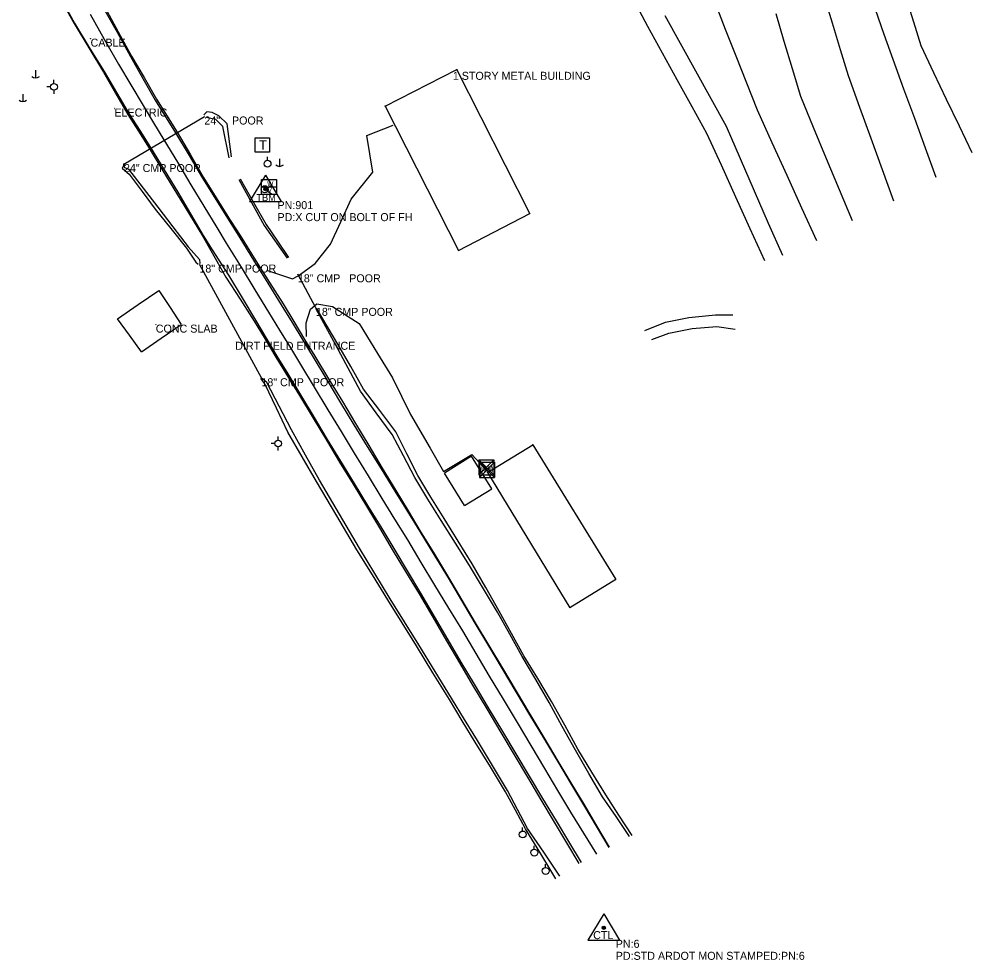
# Model space of a CAD drawing. Extents: x 1734049 to 1769984, y 344166 to 379510.
# Drawn here: x 1736178 to 1736774, y 377458 to 378046 of the extents above; entities that cross this region are included whole.
import ezdxf

# ---------------------------------------------------------------- set-up
doc = ezdxf.new("R2010")
doc.units = 0
for name, color, linetype in [('S_BUILDING', 7, 'Continuous'), ('S_CROSS_DRAIN', 7, 'Continuous'), ('S_CROSS_DRAIN_ANNOT', 7, 'Continuous'), ('S_DITCHLINE', 7, 'Continuous'), ('S_DRG_PT_SYM', 7, 'Continuous'), ('S_DRIVEWAY', 7, 'Continuous'), ('S_EDGE_CONCRETE', 7, 'Continuous'), ('S_EDGE_PAVEMENT', 7, 'Continuous'), ('S_ELECTRIC_UTILITIES_ANNOT', 7, 'Continuous'), ('S_MSC_PT_SYM', 7, 'Continuous'), ('S_PAVEMENT_CROWN', 7, 'Continuous'), ('S_PRIMARY_CTL', 7, 'Continuous'), ('S_PRIMARY_CTL_ANNOT', 7, 'Continuous'), ('S_SHOULDER', 7, 'Continuous'), ('S_SIDE_DRAIN', 7, 'Continuous'), ('S_SIDE_DRAIN_ANNOT', 7, 'Continuous'), ('S_STR_PT_SYM', 7, 'Continuous'), ('S_STREAM', 7, 'Continuous'), ('S_SURVEY_TEXT_ANNOT', 7, 'Continuous'), ('S_TELEPHONE_UTILITIES', 7, 'Continuous'), ('S_TRAILS', 7, 'Continuous'), ('S_UTILITY_POLE', 7, 'Continuous'), ('S_UTL_PT_SYM', 7, 'Continuous'), ('S_WATER_UTILITIES', 7, 'Continuous')]:
    doc.layers.add(name, color=color, linetype=linetype)

msp = doc.modelspace()

# ---------------------------------------------------------------- linework, layer by layer
at = {"layer": 'S_BUILDING'}
for p, q in [((1736407.06, 377991.82), (1736451.95, 378014.7)), ((1736497.58, 377924.73), (1736451.95, 378014.7)), ((1736407.06, 377991.82), (1736452.99, 377901.55)), ((1736452.99, 377901.55), (1736497.58, 377924.73)), ((1736471.16, 377762.94), (1736499.35, 377780.23)), ((1736499.35, 377780.23), (1736551.19, 377696.06)), ((1736471.16, 377762.94), (1736522.51, 377678.34)), ((1736551.19, 377696.06), (1736522.51, 377678.34))]:
    msp.add_line(p, q, dxfattribs=at)
at = {"layer": 'S_CROSS_DRAIN'}
msp.add_line((1736243.87, 377955.57), (1736294.14, 377985.27), dxfattribs=at)
at = {"layer": 'S_DITCHLINE'}
for points in [[(1736311.18, 377960.13), (1736308.43, 377980.73), (1736303.24, 377985.59), (1736299.03, 377987.68), (1736295.57, 377988.23), (1736293.81, 377986.28)], [(1736309.61, 377959.44), (1736305.68, 377979.09), (1736301.29, 377983.37), (1736297.18, 377984.2), (1736295.15, 377984.75)], [(1736243.79, 377955.98), (1736243.28, 377954.19), (1736242.84, 377952.93), (1736244.36, 377951.44), (1736247.07, 377949.28), (1736255.27, 377938.36), (1736263.47, 377927.43), (1736273.23, 377915.21), (1736283, 377902.99), (1736288.74, 377894.32), (1736290.32, 377893.02)], [(1736244.24, 377955), (1736243.85, 377953.55), (1736246.66, 377952.34), (1736255.8, 377940.52), (1736264.94, 377928.71), (1736274.46, 377916.25), (1736283.98, 377903.79), (1736291.09, 377895.86), (1736291.37, 377893.39)], [(1736315.57, 377945.98), (1736323.57, 377931.63), (1736331.57, 377917.27), (1736345.79, 377896.77)], [(1736316.45, 377946.31), (1736324.58, 377932.05), (1736332.7, 377917.78), (1736339.73, 377907.44), (1736346.76, 377897.09)], [(1736559.85, 377535.39), (1736551.4, 377547.84), (1736542.95, 377560.29), (1736534.46, 377574.82), (1736525.98, 377589.35), (1736517.83, 377604.23), (1736509.69, 377619.11), (1736501.21, 377633.49), (1736492.74, 377647.87), (1736484.98, 377661.79), (1736477.23, 377675.7), (1736468.52, 377690.28), (1736459.8, 377704.85), (1736450.97, 377718.81), (1736442.13, 377732.78), (1736433.84, 377746.29), (1736425.56, 377759.81), (1736418.54, 377773.18), (1736411.52, 377786.54), (1736401.58, 377800.15), (1736391.64, 377813.75), (1736384, 377828.07), (1736376.36, 377842.39), (1736370.08, 377853.81), (1736363.8, 377865.23)], [(1736561.46, 377536.06), (1736553.24, 377548.77), (1736545.01, 377561.48), (1736536.28, 377575.73), (1736527.55, 377589.98), (1736519.34, 377604.94), (1736511.14, 377619.89), (1736502.43, 377634.14), (1736493.72, 377648.39), (1736486.06, 377662.27), (1736478.39, 377676.15), (1736469.95, 377690.94), (1736461.51, 377705.73), (1736452.7, 377719.89), (1736443.89, 377734.05), (1736435.68, 377747.47), (1736427.47, 377760.89), (1736420.65, 377774.58), (1736413.83, 377788.28), (1736403.71, 377801.58), (1736393.59, 377814.88), (1736385.56, 377828.99), (1736377.53, 377843.1), (1736370.9, 377854.35), (1736364.27, 377865.61)], [(1736513.77, 377509.09), (1736504.35, 377524.65), (1736494.92, 377540.21), (1736488.62, 377551.81), (1736482.31, 377563.41), (1736472.85, 377578.92), (1736463.39, 377594.43), (1736455.31, 377607.74), (1736447.23, 377621.05), (1736437.01, 377637.79), (1736426.78, 377654.52), (1736417.81, 377668.86), (1736408.84, 377683.21), (1736399.17, 377698.84), (1736389.51, 377714.48), (1736376.81, 377735.81), (1736364.1, 377757.15), (1736355.19, 377772.6), (1736346.28, 377788.06), (1736339.12, 377803.13), (1736331.95, 377818.2), (1736330.04, 377820.85), (1736329.48, 377821.63)], [(1736516.34, 377510.77), (1736506.23, 377525.66), (1736496.12, 377540.55), (1736489.87, 377552.35), (1736483.62, 377564.14), (1736474.23, 377579.77), (1736464.84, 377595.39), (1736456.7, 377608.64), (1736448.56, 377621.89), (1736438.35, 377638.56), (1736428.13, 377655.24), (1736419.17, 377669.61), (1736410.21, 377683.98), (1736400.64, 377699.78), (1736391.06, 377715.59), (1736378.57, 377736.79), (1736366.09, 377757.99), (1736357.36, 377773.72), (1736348.63, 377789.44), (1736340.9, 377804.26), (1736333.18, 377819.07), (1736330.38, 377821.44), (1736330.03, 377821.84)]]:
    msp.add_lwpolyline(points, dxfattribs=at)
at = {"layer": 'S_DRG_PT_SYM'}
for points in [[(1736294.14, 377985.27), (1736294.14, 377985.32), (1736294.14, 377985.27), (1736294.09, 377985.27), (1736294.14, 377985.27), (1736294.14, 377985.22), (1736294.14, 377985.27), (1736294.19, 377985.27)], [(1736243.87, 377955.57), (1736243.87, 377955.62), (1736243.87, 377955.57), (1736243.82, 377955.57), (1736243.87, 377955.57), (1736243.87, 377955.52), (1736243.87, 377955.57), (1736243.92, 377955.57)], [(1736291.01, 377892.78), (1736291.01, 377892.83), (1736291.01, 377892.78), (1736290.96, 377892.78), (1736291.01, 377892.78), (1736291.01, 377892.73), (1736291.01, 377892.78), (1736291.06, 377892.78)], [(1736352.57, 377886.68), (1736352.57, 377886.73), (1736352.57, 377886.68), (1736352.52, 377886.68), (1736352.57, 377886.68), (1736352.57, 377886.63), (1736352.57, 377886.68), (1736352.62, 377886.68)], [(1736363.84, 377865.72), (1736363.84, 377865.77), (1736363.84, 377865.72), (1736363.79, 377865.72), (1736363.84, 377865.72), (1736363.84, 377865.67), (1736363.84, 377865.72), (1736363.89, 377865.72)], [(1736329.77, 377821.75), (1736329.77, 377821.8), (1736329.77, 377821.75), (1736329.72, 377821.75), (1736329.77, 377821.75), (1736329.77, 377821.7), (1736329.77, 377821.75), (1736329.82, 377821.75)]]:
    msp.add_lwpolyline(points, dxfattribs=at)
at = {"layer": 'S_DRIVEWAY'}
for points in [[(1736332.86, 377889.34), (1736349.22, 377883.93), (1736352.82, 377885.81), (1736363.37, 377893.49), (1736372.94, 377905.43), (1736379.42, 377919.56), (1736385.9, 377933.69), (1736399.34, 377950.44), (1736395.72, 377973.3), (1736412.14, 377979.85)], [(1736357.92, 377847.85), (1736357.81, 377856.36), (1736360.41, 377865), (1736364.36, 377868.33), (1736374.28, 377866.51), (1736390.96, 377855.95), (1736402.39, 377837.13), (1736411.65, 377822.05), (1736417.25, 377810.55), (1736422.85, 377799.06), (1736435.17, 377778.14), (1736443.53, 377763.58), (1736461.32, 377774.13), (1736471.11, 377763.53)]]:
    msp.add_lwpolyline(points, dxfattribs=at)
at = {"layer": 'S_EDGE_CONCRETE'}
for points in [[(1736254.73, 377838.24), (1736247.3, 377848.59), (1736239.86, 377858.93), (1736252.81, 377867.77), (1736265.76, 377876.61), (1736272.7, 377865.93), (1736279.65, 377855.25)], [(1736254.73, 377838.24), (1736267.19, 377846.74), (1736279.65, 377855.25)], [(1736456.77, 377742.17), (1736473.7, 377752.55), (1736461.04, 377773.03), (1736444.19, 377762.54)], [(1736456.77, 377742.17), (1736444.19, 377762.54)]]:
    msp.add_lwpolyline(points, dxfattribs=at)
at = {"layer": 'S_EDGE_PAVEMENT'}
for points in [[(1736202.97, 378061.85), (1736212.99, 378043.66), (1736222.2, 378028.48), (1736231.41, 378013.31), (1736239.21, 378000.18), (1736247, 377987.06), (1736253.71, 377976.45), (1736260.42, 377965.85), (1736268.94, 377951.87), (1736277.46, 377937.9), (1736285.46, 377924.42), (1736293.47, 377910.93), (1736299.04, 377902.04), (1736309.15, 377886.04), (1736317.64, 377872.04), (1736326.14, 377858.04), (1736332.83, 377846.75), (1736339.51, 377835.46), (1736345.59, 377825.52), (1736354.13, 377811.32), (1736362.67, 377797.12), (1736370.97, 377783.49), (1736379.27, 377769.86), (1736387.69, 377756.08), (1736396.11, 377742.3), (1736404.35, 377728.88), (1736412.58, 377715.47), (1736420.85, 377701.52), (1736429.11, 377687.57), (1736437.68, 377672.91), (1736446.26, 377658.25), (1736454.5, 377644.42), (1736462.74, 377630.6), (1736471.59, 377615.84), (1736480.43, 377601.09), (1736488.75, 377587.1), (1736497.07, 377573.11), (1736505.52, 377559.17), (1736513.97, 377545.24), (1736521.79, 377532.24), (1736529.61, 377519.24)], [(1736231.18, 378053.03), (1736239.54, 378037.86), (1736247.91, 378022.69), (1736255.69, 378009.1), (1736263.46, 377995.51), (1736276.16, 377975.1), (1736284.59, 377960.91), (1736293.02, 377946.71), (1736301.34, 377933.42), (1736309.66, 377920.14), (1736315.65, 377910.5), (1736325.41, 377894.49), (1736333.8, 377881.06), (1736342.19, 377867.63), (1736348.92, 377856.54), (1736355.64, 377845.45), (1736362.02, 377834.87), (1736370.63, 377820.65), (1736379.23, 377806.42), (1736387.6, 377792.72), (1736395.96, 377779.01), (1736404.57, 377765.11), (1736413.19, 377751.21), (1736421, 377738.58), (1736428.81, 377725.95), (1736437.6, 377711.53), (1736446.39, 377697.11), (1736454.73, 377682.9), (1736463.07, 377668.69), (1736471.69, 377654.47), (1736480.3, 377640.25), (1736488.86, 377625.9), (1736497.42, 377611.54), (1736506.09, 377596.99), (1736514.76, 377582.43), (1736522.87, 377568.86), (1736530.97, 377555.28), (1736538.97, 377541.97), (1736546.96, 377528.66)]]:
    msp.add_lwpolyline(points, dxfattribs=at)
at = {"layer": 'S_MSC_PT_SYM'}
for points in [[(1736449.41, 378013.18), (1736449.41, 378013.23), (1736449.41, 378013.18), (1736449.36, 378013.18), (1736449.41, 378013.18), (1736449.41, 378013.13), (1736449.41, 378013.18), (1736449.46, 378013.18)], [(1736263.75, 377855.25), (1736263.75, 377855.3), (1736263.75, 377855.25), (1736263.7, 377855.25), (1736263.75, 377855.25), (1736263.75, 377855.2), (1736263.75, 377855.25), (1736263.8, 377855.25)], [(1736313.42, 377844.52), (1736313.42, 377844.57), (1736313.42, 377844.52), (1736313.37, 377844.52), (1736313.42, 377844.52), (1736313.42, 377844.47), (1736313.42, 377844.52), (1736313.47, 377844.52)]]:
    msp.add_lwpolyline(points, dxfattribs=at)
at = {"layer": 'S_PAVEMENT_CROWN'}
msp.add_lwpolyline([(1736222.68, 378049.1), (1736231.55, 378033.57), (1736240.41, 378018.04), (1736248.09, 378005.04), (1736255.78, 377992.05), (1736262.25, 377981.34), (1736268.72, 377970.63), (1736277.24, 377956.66), (1736285.76, 377942.68), (1736293.85, 377929.28), (1736301.93, 377915.87), (1736307.8, 377906.2), (1736317.05, 377891.05), (1736325.62, 377877.01), (1736334.19, 377862.98), (1736341.05, 377851.81), (1736347.92, 377840.64), (1736354.22, 377830.31), (1736362.77, 377816.12), (1736371.31, 377801.93), (1736379.55, 377788.43), (1736387.78, 377774.93), (1736396.46, 377760.8), (1736405.13, 377746.67), (1736413.05, 377733.72), (1736420.97, 377720.77), (1736429.51, 377706.64), (1736438.04, 377692.5), (1736446.73, 377678.18), (1736455.42, 377663.86), (1736463.76, 377649.77), (1736472.1, 377635.67), (1736480.85, 377621.2), (1736489.6, 377606.72), (1736498.17, 377592.29), (1736506.75, 377577.86), (1736514.89, 377564.23), (1736523.02, 377550.59), (1736531.06, 377537.48), (1736539.1, 377524.37)], dxfattribs=at)
at = {"layer": 'S_PRIMARY_CTL'}
for p, q in [((1736332.32, 377948.6), (1736322.29, 377932.09)), ((1736332.32, 377948.6), (1736342.15, 377932.09)), ((1736322.29, 377932.09), (1736342.15, 377932.09)), ((1736543.71, 377487.1), (1736533.68, 377470.59)), ((1736543.71, 377487.1), (1736553.54, 377470.59)), ((1736533.68, 377470.59), (1736553.54, 377470.59))]:
    msp.add_line(p, q, dxfattribs=at)
for centre, radius in [((1736332.32, 377939.9), 1.04), ((1736332.32, 377939.9), 0.609), ((1736332.32, 377939.9), 0.344), ((1736543.71, 377478.4), 1.04), ((1736543.71, 377478.4), 0.609), ((1736543.71, 377478.4), 0.344)]:
    msp.add_circle(centre, radius, dxfattribs=at)
at = {"layer": 'S_SHOULDER'}
for points in [[(1736202.57, 378061.64), (1736212.65, 378043.47), (1736221.83, 378028.26), (1736231, 378013.04), (1736238.67, 377999.83), (1736246.34, 377986.62), (1736252.99, 377976.01), (1736259.64, 377965.4), (1736268.18, 377951.42), (1736276.73, 377937.43), (1736284.88, 377924.05), (1736293.02, 377910.67), (1736298.13, 377901.46), (1736307.54, 377884.97), (1736316.42, 377871.21), (1736325.31, 377857.46), (1736332.04, 377846.19), (1736338.77, 377834.93), (1736344.82, 377825.08), (1736353.49, 377810.94), (1736362.15, 377796.79), (1736370.39, 377783.1), (1736378.63, 377769.41), (1736387.07, 377755.6), (1736395.51, 377741.79), (1736403.5, 377728.3), (1736411.49, 377714.82), (1736419.9, 377700.92), (1736428.32, 377687.02), (1736436.9, 377672.39), (1736445.48, 377657.77), (1736453.64, 377643.87), (1736461.8, 377629.98), (1736470.64, 377615.23), (1736479.49, 377600.49), (1736487.81, 377586.49), (1736496.14, 377572.5), (1736504.42, 377558.46), (1736512.7, 377544.42), (1736520.47, 377531.47), (1736528.24, 377518.52)], [(1736231.88, 378053.49), (1736240.27, 378038.26), (1736248.66, 378023.03), (1736256.45, 378009.6), (1736264.24, 377996.18), (1736277.08, 377975.56), (1736285.35, 377961.33), (1736293.62, 377947.1), (1736301.89, 377933.77), (1736310.17, 377920.43), (1736316.39, 377911.02), (1736326.19, 377895.02), (1736334.81, 377881.62), (1736343.42, 377868.23), (1736350.11, 377857.12), (1736356.8, 377846.01), (1736363.08, 377835.52), (1736371.78, 377821.33), (1736380.47, 377807.14), (1736388.65, 377793.46), (1736396.83, 377779.79), (1736405.28, 377765.65), (1736413.73, 377751.52), (1736421.41, 377738.91), (1736429.08, 377726.29), (1736437.91, 377711.81), (1736446.74, 377697.32), (1736455.06, 377683.11), (1736463.37, 377668.91), (1736471.88, 377654.76), (1736480.39, 377640.6), (1736488.99, 377626.22), (1736497.6, 377611.84), (1736506.33, 377597.22), (1736515.07, 377582.6), (1736523.17, 377569.08), (1736531.28, 377555.55), (1736539.2, 377542.18), (1736547.12, 377528.82)]]:
    msp.add_lwpolyline(points, dxfattribs=at)
at = {"layer": 'S_SIDE_DRAIN'}
for p, q in [((1736291.01, 377892.78), (1736329.77, 377821.75)), ((1736363.84, 377865.72), (1736352.57, 377886.68))]:
    msp.add_line(p, q, dxfattribs=at)
at = {"layer": 'S_STR_PT_SYM'}
for points in [[(1736451.95, 378014.7), (1736451.95, 378014.75), (1736451.95, 378014.7), (1736451.9, 378014.7), (1736451.95, 378014.7), (1736451.95, 378014.65), (1736451.95, 378014.7), (1736452, 378014.7)], [(1736451.95, 378014.7), (1736451.95, 378014.75), (1736451.95, 378014.7), (1736451.9, 378014.7), (1736451.95, 378014.7), (1736451.95, 378014.65), (1736451.95, 378014.7), (1736452, 378014.7)], [(1736407.06, 377991.82), (1736407.06, 377991.87), (1736407.06, 377991.82), (1736407.01, 377991.82), (1736407.06, 377991.82), (1736407.06, 377991.77), (1736407.06, 377991.82), (1736407.11, 377991.82)], [(1736407.06, 377991.82), (1736407.06, 377991.87), (1736407.06, 377991.82), (1736407.01, 377991.82), (1736407.06, 377991.82), (1736407.06, 377991.77), (1736407.06, 377991.82), (1736407.11, 377991.82)], [(1736497.58, 377924.73), (1736497.58, 377924.78), (1736497.58, 377924.73), (1736497.53, 377924.73), (1736497.58, 377924.73), (1736497.58, 377924.68), (1736497.58, 377924.73), (1736497.63, 377924.73)], [(1736452.99, 377901.55), (1736452.99, 377901.6), (1736452.99, 377901.55), (1736452.94, 377901.55), (1736452.99, 377901.55), (1736452.99, 377901.5), (1736452.99, 377901.55), (1736453.04, 377901.55)], [(1736499.35, 377780.23), (1736499.35, 377780.28), (1736499.35, 377780.23), (1736499.3, 377780.23), (1736499.35, 377780.23), (1736499.35, 377780.18), (1736499.35, 377780.23), (1736499.4, 377780.23)], [(1736471.16, 377762.94), (1736471.16, 377762.99), (1736471.16, 377762.94), (1736471.11, 377762.94), (1736471.16, 377762.94), (1736471.16, 377762.89), (1736471.16, 377762.94), (1736471.21, 377762.94)], [(1736471.16, 377762.94), (1736471.16, 377762.99), (1736471.16, 377762.94), (1736471.11, 377762.94), (1736471.16, 377762.94), (1736471.16, 377762.89), (1736471.16, 377762.94), (1736471.21, 377762.94)], [(1736551.19, 377696.06), (1736551.19, 377696.11), (1736551.19, 377696.06), (1736551.14, 377696.06), (1736551.19, 377696.06), (1736551.19, 377696.01), (1736551.19, 377696.06), (1736551.24, 377696.06)], [(1736522.51, 377678.34), (1736522.51, 377678.39), (1736522.51, 377678.34), (1736522.46, 377678.34), (1736522.51, 377678.34), (1736522.51, 377678.29), (1736522.51, 377678.34), (1736522.56, 377678.34)], [(1736522.51, 377678.34), (1736522.51, 377678.39), (1736522.51, 377678.34), (1736522.46, 377678.34), (1736522.51, 377678.34), (1736522.51, 377678.29), (1736522.51, 377678.34), (1736522.56, 377678.34)]]:
    msp.add_lwpolyline(points, dxfattribs=at)
at = {"layer": 'S_STREAM'}
for points in [[(1736562.24, 378058.44), (1736570.99, 378041.76), (1736580.23, 378025.04), (1736589.47, 378008.32), (1736598.72, 377991.59), (1736607.96, 377974.87), (1736617.01, 377954.98), (1736626.05, 377935.09), (1736635.1, 377915.2), (1736644.14, 377895.31)], [(1736613.05, 378056.67), (1736619.68, 378039.88), (1736626.31, 378023.1), (1736632.95, 378006.31), (1736639.58, 377989.52), (1736648.85, 377969.08), (1736658.12, 377948.64), (1736667.39, 377928.2), (1736676.65, 377907.76)], [(1736681.58, 378060.15), (1736686.54, 378043.69), (1736691.5, 378027.23), (1736696.46, 378010.78), (1736703.53, 377991.2), (1736710.6, 377971.63), (1736717.67, 377952.06), (1736724.74, 377932.48)], [(1736732.77, 378059.2), (1736737.29, 378044.38), (1736741.81, 378029.55), (1736749.82, 378012.84), (1736757.83, 377996.14), (1736765.83, 377979.43), (1736773.84, 377962.72)], [(1736651.18, 378049.6), (1736656.33, 378032.41), (1736661.47, 378015.22), (1736666.62, 377998.02), (1736674.7, 377978.57), (1736682.78, 377959.11), (1736690.86, 377939.66), (1736698.94, 377920.2)], [(1736713.3, 378052.38), (1736718.85, 378036.73), (1736724.41, 378021.08), (1736731.14, 378002.64), (1736737.87, 377984.2), (1736744.61, 377965.76), (1736751.34, 377947.32)], [(1736581.88, 378048.31), (1736591.46, 378031.02), (1736601.04, 378013.73), (1736610.63, 377996.44), (1736620.21, 377979.16), (1736629, 377959), (1736637.79, 377938.85), (1736646.58, 377918.7), (1736655.37, 377898.54)]]:
    msp.add_lwpolyline(points, dxfattribs=at)
at = {"layer": 'S_TELEPHONE_UTILITIES'}
msp.add_lwpolyline([(1736325.79, 377962.95), (1736325.79, 377971.95), (1736334.79, 377971.95), (1736334.79, 377962.95)], close=True, dxfattribs=at)
at = {"layer": 'S_TRAILS'}
for points in [[(1736569.33, 377851.49), (1736582.32, 377856.71), (1736596.89, 377859.78), (1736613.52, 377861.45), (1736624.42, 377861.3)], [(1736573.87, 377845.97), (1736584.5, 377849.85), (1736598.97, 377852.91), (1736614.41, 377854.16), (1736625.77, 377852.38)]]:
    msp.add_lwpolyline(points, dxfattribs=at)
at = {"layer": 'S_UTILITY_POLE'}
for p, q in [((1736188.58, 378014.14), (1736188.58, 378009.41)), ((1736200.12, 378005.91), (1736200.12, 378008.16)), ((1736198.03, 378003.78), (1736195.7, 378003.78)), ((1736200.2, 377999.36), (1736200.2, 378001.69)), ((1736180.59, 377999.28), (1736180.59, 377994.55)), ((1736333.49, 377957.93), (1736333.49, 377960.04)), ((1736341.09, 377958.83), (1736341.09, 377954.1)), ((1736338.14, 377780.94), (1736335.81, 377780.94)), ((1736340.23, 377783.07), (1736340.23, 377785.32)), ((1736340.31, 377776.52), (1736340.31, 377778.85)), ((1736492.94, 377538.89), (1736492.94, 377541)), ((1736500.17, 377527.5), (1736500.17, 377529.61)), ((1736507.29, 377516.09), (1736507.29, 377518.19))]:
    msp.add_line(p, q, dxfattribs=at)
for centre in [(1736200.12, 378003.8), (1736333.62, 377955.79), (1736340.23, 377780.96), (1736493.07, 377536.75), (1736500.3, 377525.36), (1736507.41, 377513.94)]:
    msp.add_circle(centre, 2.13, dxfattribs=at)
for centre in [(1736188.64, 378012.83), (1736180.66, 377997.98), (1736341.15, 377957.53)]:
    msp.add_arc(centre, 3.41, 226.39718, 313.60282, dxfattribs=at)
at = {"layer": 'S_UTL_PT_SYM'}
for points in [[(1736223.01, 378033.9), (1736223.01, 378033.95), (1736223.01, 378033.9), (1736222.96, 378033.9), (1736223.01, 378033.9), (1736223.01, 378033.85), (1736223.01, 378033.9), (1736223.06, 378033.9)], [(1736237.89, 377990.26), (1736237.89, 377990.31), (1736237.89, 377990.26), (1736237.84, 377990.26), (1736237.89, 377990.26), (1736237.89, 377990.21), (1736237.89, 377990.26), (1736237.94, 377990.26)]]:
    msp.add_lwpolyline(points, dxfattribs=at)
at = {"layer": 'S_WATER_UTILITIES'}
for p, q in [((1736329.81, 377946.01), (1736339.23, 377946.01)), ((1736329.81, 377936.59), (1736329.81, 377946.01)), ((1736333.77, 377940.9), (1736336.59, 377942.63)), ((1736339.23, 377946.01), (1736339.23, 377936.59)), ((1736329.81, 377941.32), (1736339.23, 377941.32)), ((1736339.23, 377936.59), (1736329.81, 377936.59)), ((1736333.64, 377938.59), (1736336.55, 377936.66)), ((1736465.72, 377770.79), (1736475.06, 377770.79)), ((1736465.72, 377770.79), (1736465.72, 377761.3)), ((1736465.72, 377770.79), (1736475.06, 377761.3)), ((1736475.06, 377770.79), (1736465.72, 377761.3)), ((1736466.17, 377769.28), (1736475.51, 377769.28)), ((1736466.17, 377769.28), (1736466.17, 377759.78)), ((1736466.17, 377769.28), (1736475.51, 377759.78)), ((1736475.51, 377769.28), (1736466.17, 377759.78)), ((1736475.06, 377770.79), (1736475.06, 377761.3)), ((1736475.51, 377769.28), (1736475.51, 377759.78)), ((1736465.72, 377761.3), (1736475.06, 377761.3)), ((1736466.17, 377759.78), (1736475.51, 377759.78))]:
    msp.add_line(p, q, dxfattribs=at)
msp.add_circle((1736331.86, 377939.84), 2.18, dxfattribs=at)

# ---------------------------------------------------------------- texts
at = {"layer": 'S_CROSS_DRAIN_ANNOT'}
for s, p in [('24"    POOR ', (1736294.14, 377980.27)), ('24" CMP POOR', (1736243.87, 377950.57))]:
    msp.add_text(s, height=5, dxfattribs=at).set_placement(p)
at = {"layer": 'S_ELECTRIC_UTILITIES_ANNOT'}
for s, p in [('CABLE', (1736223.01, 378028.9)), ('ELECTRIC', (1736237.89, 377985.26))]:
    msp.add_text(s, height=5, dxfattribs=at).set_placement(p)
at = {"layer": 'S_PRIMARY_CTL'}
for s, height, p in [('TBM', 4.287, (1736326.67, 377932.51)), ('CTL', 5, (1736537.13, 377471.33))]:
    msp.add_text(s, height=height, rotation=360, dxfattribs=at).set_placement(p)
at = {"layer": 'S_PRIMARY_CTL_ANNOT'}
for s, p in [('PN:901', (1736339.82, 377927.4)), ('PD:X CUT ON BOLT OF FH', (1736339.82, 377919.9)), ('PN:6', (1736551.22, 377465.9)), ('PD:STD ARDOT MON STAMPED:PN:6', (1736551.22, 377458.4))]:
    msp.add_text(s, height=5, dxfattribs=at).set_placement(p)
at = {"layer": 'S_SIDE_DRAIN_ANNOT'}
for s, p in [('18" CMP POOR', (1736291.01, 377887.78)), ('18" CMP   POOR ', (1736352.57, 377881.68)), ('18" CMP POOR', (1736363.84, 377860.72)), ('18" CMP   POOR ', (1736329.77, 377816.75))]:
    msp.add_text(s, height=5, dxfattribs=at).set_placement(p)
at = {"layer": 'S_SURVEY_TEXT_ANNOT'}
for s, p in [('1 STORY METAL BUILDING', (1736449.41, 378008.18)), ('CONC SLAB', (1736263.75, 377850.25)), ('DIRT FIELD ENTRANCE', (1736313.42, 377839.52))]:
    msp.add_text(s, height=5, dxfattribs=at).set_placement(p)
at = {"layer": 'S_TELEPHONE_UTILITIES'}
msp.add_text('T', height=6, rotation=360, dxfattribs=at).set_placement((1736328.35, 377964.45))
at = {"layer": 'S_WATER_UTILITIES'}
for s, p in [('W', (1736333.36, 377941.85)), ('V', (1736333.6, 377937.79)), ('W M', (1736465.93, 377764.55)), ('W M', (1736466.37, 377763.04))]:
    msp.add_text(s, height=3, rotation=360, dxfattribs=at).set_placement(p)

doc.saveas('drawing.dxf')
